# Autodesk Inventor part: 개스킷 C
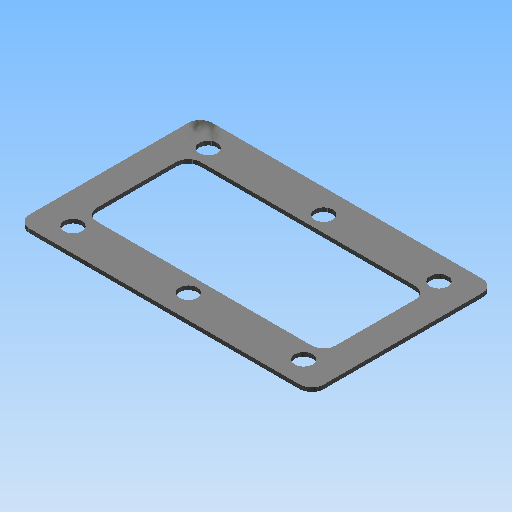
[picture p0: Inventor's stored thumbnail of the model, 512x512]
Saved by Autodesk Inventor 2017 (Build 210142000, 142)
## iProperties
Created: 2020-04
Part Number: 개스킷 C
Material: 고무
Document SubType Name: Modeling
Designer: mduedu
Density: 0.93 g/cm^3
Appearance: 고무 - 검은색 - 버전 1.1
Mass: 1.62617 g
Surface Area: 39.8367 cm^2
Volume: 1.74857 cm^3
Author: mduedu
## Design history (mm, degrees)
sketch "스케치1"
  geometry: L1 (37, 23)-(-37, 23); L2 (-37, 23)-(-37, -23); L3 (-37, -23)-(37, -23); L4 (37, -23)-(37, 23); L5 (37, 23)-(-37, -23); L6 (-37, 23)-(37, -23); L7 (30, 13)-(-30, 13); L8 (-30, 13)-(-30, -13); L9 (-30, -13)-(30, -13); L10 (30, -13)-(30, 13); L11 (30, 13)-(-30, -13); L12 (-30, 13)-(30, -13); 1 further point
  constraints: 24 end point, 4 midpoint, 4 parallel, 2 horizontal, 2 perpendicular
  dimensions: "d0" = 74 distance of L3.end L2.end; "d1" = 46 distance of L2.end L1.end; "d2" = 60 distance of L9.end L8.end; "d3" = 26 distance of L8.end L7.end
extrude "돌출1" new body sketch "스케치1" distance "d4" = 1; taper "d5" = 0 deg
fillet "모깎기1" dims "d6" = 3
fillet "모깎기2" dims "d7" = 3
sketch "스케치2"
  geometry: L1 (-29, -17)-(29, -17); L2 (29, -17)-(29, 17); L3 (29, 17)-(-29, 17); L4 (-29, 17)-(-29, -17); L5 (-29, -17)-(29, 17); L6 (29, -17)-(-29, 17); 7 further points
  constraints: 12 end point, 4 coincident, 4 midpoint, 2 parallel, 1 horizontal, 1 perpendicular
  dimensions: "d8" = 58 distance of L3.end L2.end; "d9" = 34 distance of L2.end L1.end
hole "구멍1" sketch "스케치2" at (-29, 17), (29, 17), (29, -17), (-29, -17), (0, 17), (0, -17) diameter "d10" = 4.5; stored, may be unused: countersink angle "d14" = 90 deg, drill point angle "d16" = 118 deg; dims "d11" = 6, "d12" = 4, "d13" = 2, "d15" = 8
node "솔리드1"
